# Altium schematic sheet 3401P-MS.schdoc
size 127 x 101 mm
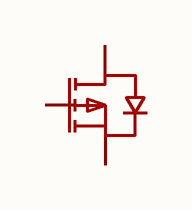
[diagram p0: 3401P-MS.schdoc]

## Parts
Q?  3401p-ms  [SOT-89-3_L4.5-W2.5-P1.50-LS4.2-BR]  (value not drawn)

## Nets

Not connected (* = marked no-connect by the designer): Q? 1(G) 2(D) 3(S)

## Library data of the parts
Q? = 3401p-ms: 数量:1个P沟道;漏源电压(Vdss):30V;连续漏极电流(Id):4.2A;导通电阻(RDS(on)):42mΩ@10V;耗散功率(Pd):1.2W;阈值电压(Vgs(th)):1V;; Manufacturer: MSKSEMI(美森科); AddInBom: yes; ModelId: 6db690b7897d4d18a30d90c1b89525ee; ModelName: SOT-89-3_L4.3-W2.5-H1.6-LS4.1-P1.50; ModelTransform: 161.417,169.291,0,180,0,0,-18.661,0,0; Number: 1个P沟道; Drain to Source Voltage: 30V; Current - Continuous Drain(Id): 4.2A; Pd - Power Dissipation: 1.2W; Gate Threshold Voltage (Vgs(th)): 1V; Gate Charge(Qg): 9.5nC@4.5V; Input Capacitance(Ciss): 950pF; Reverse Transfer Capacitance (Crss@Vds): 75pF; Type: P沟道; Output Capacitance(Coss): 115pF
